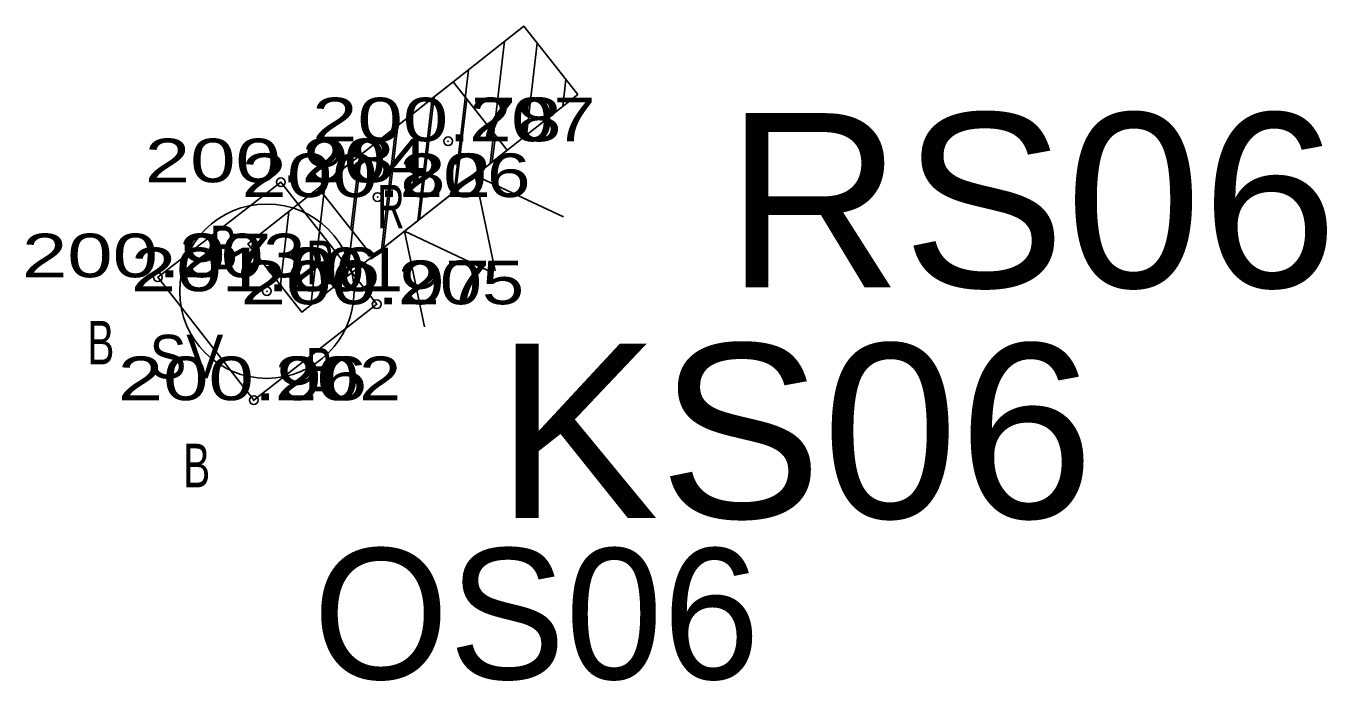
# Model space of a CAD drawing. Extents: x -465254 to -463400, y -1095454 to -1094005.
# Drawn here: x -465027.82 to -465012.9, y -1095285.06 to -1095277.55 of the extents above; entities that cross this region are included whole.
import ezdxf
from ezdxf.enums import TextEntityAlignment as Align

# ---------------------------------------------------------------- set-up
doc = ezdxf.new("R2010")
doc.units = 0
doc.header["$LTSCALE"] = 0.2
doc.header["$PDMODE"] = 32
doc.header["$PDSIZE"] = 0.1
for name, color, linetype in [('1', 7, 'Continuous'), ('2', 7, 'Continuous'), ('3', 7, 'Continuous'), ('4', 7, 'Continuous')]:
    doc.layers.add(name, color=color, linetype=linetype)
for name, color, linetype, lineweight in [('12', 7, 'Continuous', 25), ('25', 7, 'Continuous', 25), ('33', 7, 'Continuous', 25)]:
    doc.layers.add(name, color=color, linetype=linetype, lineweight=lineweight)

msp = doc.modelspace()

# ---------------------------------------------------------------- linework, layer by layer
at = {"layer": '1'}
for p in [(-465022.98, -1095278.87), (-465024.9, -1095279.34), (-465023.79, -1095279.51), (-465026.31, -1095280.43), (-465025.06, -1095280.59), (-465023.8, -1095280.74), (-465025.21, -1095281.84)]:
    msp.add_point(p, dxfattribs=at)
at = {"layer": '12'}
msp.add_lwpolyline([(-465024.9, -1095279.34), (-465023.8, -1095280.74), (-465025.21, -1095281.84), (-465026.31, -1095280.43)], close=True, dxfattribs=at)
at = {"layer": '25'}
msp.add_circle((-465025.06, -1095280.59), 1, dxfattribs=at)
at = {"layer": '33'}
for p, q in [((-465022.332, -1095277.721), (-465022.497, -1095279.125)), ((-465021.957, -1095277.745), (-465022.08, -1095278.796)), ((-465022.748, -1095278.049), (-465022.912, -1095279.454)), ((-465021.628, -1095278.161), (-465021.664, -1095278.468)), ((-465023.164, -1095278.378), (-465023.328, -1095279.782)), ((-465023.141, -1095278.361), (-465023.308, -1095279.766)), ((-465022.766, -1095278.386), (-465022.89, -1095279.437)), ((-465023.58, -1095278.707), (-465023.745, -1095280.112)), ((-465023.558, -1095278.689), (-465023.722, -1095280.094)), ((-465022.438, -1095278.802), (-465022.473, -1095279.108)), ((-465023.973, -1095279.018), (-465024.139, -1095280.422)), ((-465023.996, -1095279.036), (-465024.095, -1095279.878)), ((-465024.39, -1095279.347), (-465024.556, -1095280.75)), ((-465024.412, -1095279.364), (-465024.424, -1095279.463)), ((-465024.807, -1095279.675), (-465024.905, -1095280.518)), ((-465025.222, -1095280.003), (-465025.233, -1095280.102))]:
    msp.add_line(p, q, dxfattribs=at)
for points in [[(-465021.493, -1095278.332), (-465023.847, -1095280.192), (-465024.467, -1095279.408), (-465022.113, -1095277.548)], [(-465021.493, -1095278.332), (-465023.847, -1095280.192), (-465024.467, -1095279.408), (-465022.113, -1095277.548)], [(-465022.302, -1095278.973), (-465024.658, -1095280.832), (-465025.278, -1095280.047), (-465022.922, -1095278.188)], [(-465022.302, -1095278.973), (-465024.658, -1095280.832), (-465025.278, -1095280.047), (-465022.922, -1095278.188)]]:
    msp.add_lwpolyline(points, close=True, dxfattribs=at)
for points in [[(-465021.658, -1095279.737), (-465022.67, -1095279.262), (-465022.442, -1095280.357)], [(-465022.468, -1095280.378), (-465023.48, -1095279.903), (-465023.253, -1095280.998)]]:
    msp.add_lwpolyline(points, dxfattribs=at)

# ---------------------------------------------------------------- texts
at = {"layer": '2'}
for s, width, p in [(' 207', 1.3, (-465022.98, -1095278.87)), (' 204', 1.3, (-465024.9, -1095279.34)), (' 206', 1.35, (-465023.79, -1095279.51)), (' 203', 1.3, (-465026.31, -1095280.43)), (' 201', 1.2, (-465025.06, -1095280.59)), (' 205', 1.3, (-465023.8, -1095280.74)), (' 202', 1.3, (-465025.21, -1095281.84))]:
    msp.add_text(s, height=0.5, dxfattribs=dict(at, width=width)).set_placement(p)
at = {"layer": '25'}
msp.add_text('OS06', height=1.5, dxfattribs=at).set_placement((-465021.9675, -1095285.04), align=Align.CENTER)
at = {"layer": '3', "width": 1.4}
for s, p in [('200.78 ', (-465022.9795, -1095278.87)), ('200.98 ', (-465024.8995, -1095279.34)), ('200.82 ', (-465023.7895, -1095279.51)), ('200.97 ', (-465026.3095, -1095280.43)), ('201.06 ', (-465025.0595, -1095280.59)), ('200.97 ', (-465023.7995, -1095280.74)), ('200.96 ', (-465025.2095, -1095281.84))]:
    msp.add_text(s, height=0.5, dxfattribs=at).set_placement(p, align=Align.CENTER)
at = {"layer": '33', "width": 1.05}
for s, p in [('RS06', (-465016.284, -1095280.547)), ('KS06', (-465019, -1095283.193))]:
    msp.add_text(s, height=2, dxfattribs=at).set_placement(p, align=Align.CENTER)
at = {"layer": '4'}
for s, width, p in [('R', 0.65, (-465023.48, -1095279.87)), ('B', 0.7, (-465025.4, -1095280.34)), ('R', 0.65, (-465024.29, -1095280.51)), ('B', 0.7, (-465026.81, -1095281.43)), ('SV', 0.95, (-465025.56, -1095281.59)), ('B', 0.7, (-465024.3, -1095281.74)), ('B', 0.7, (-465025.71, -1095282.84))]:
    msp.add_text(s, height=0.5, dxfattribs=dict(at, width=width)).set_placement(p, align=Align.RIGHT)

doc.saveas('drawing.dxf')
